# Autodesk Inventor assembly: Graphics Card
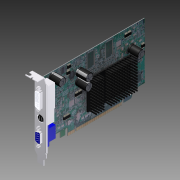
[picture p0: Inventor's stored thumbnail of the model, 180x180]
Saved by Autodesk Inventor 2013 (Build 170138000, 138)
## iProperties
Company: Autodesk Inc.
Created: 2005-12
Part Number: Graphics Card
Document SubType Name: Assembly
Designer: Autodesk Inc.
Mass: 53.2227 g
Surface Area: 677.742 cm^2
Volume: 53.2227 cm^3
Density: 1 g/cm^3
Title: Personal Computer
Author: Autodesk Inc.
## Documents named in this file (7)
- Z:\_DATEN\Personal Computer\Graphics Card\Graphics Card.iam
- Z:\_DATEN\Personal Computer\Graphics Card\Graphic Card PCB.ipt
- Z:\_DATEN\Personal Computer\Graphics Card\Graphic Card Heat Sink.ipt
- Z:\_DATEN\Personal Computer\Motherboard\Chip 5 x 3.ipt
- Z:\_DATEN\Personal Computer\Motherboard\Capacitor 3500 UF.ipt
- Z:\_DATEN\Personal Computer\Motherboard\Chip 22 x 11.ipt
- Z:\_DATEN\Personal Computer\Graphics Card\Graphic Card Sheetmetal.ipt
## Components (18 placed, 6 different names)
1. Graphic Card PCB:1 — Mate:1, Mate:2, Mate:3, Mate:4, Mate:5, Mate:6, Mate:7, Mate:8, Mate:9, Mate:10, Mate:11, Mate:12, Mate:13, Mate:14, Mate:15, Mate:16, Flush:2, Mate:18, Mate:19
2. Capacitor 3500 UF:1 — Mate:1
3. Capacitor 3500 UF:2 — Mate:2
4. Capacitor 3500 UF:3 — Mate:3
5. Graphic Card Heat Sink:1 — Mate:4
6. Capacitor 3500 UF:4 — Mate:5
7. Chip 5 x 3:1 — Mate:8
8. Chip 5 x 3:2 — Mate:7
9. Chip 5 x 3:3 — Mate:6
10. Chip 5 x 3:4 — Mate:9
11. Chip 5 x 3:5 — Mate:10
12. Chip 22 x 11:1 — Mate:11
13. Chip 22 x 11:2 — Mate:12
14. Chip 5 x 3:6 — Mate:13
15. Chip 5 x 3:7 — Mate:14
16. Chip 5 x 3:8 — Mate:15, Flush:1
17. Chip 5 x 3:9 — Mate:16, Flush:1
18. Graphic Card Sheetmetal:1 — Flush:2, Mate:18, Mate:19
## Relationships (20: Mate 18, Flush 2)
- Mate:1: Graphic Card PCB:1 ↔ Capacitor 3500 UF:1
- Mate:2: Graphic Card PCB:1 ↔ Capacitor 3500 UF:2
- Mate:3: Graphic Card PCB:1 ↔ Capacitor 3500 UF:3
- Mate:4: Graphic Card PCB:1 ↔ Graphic Card Heat Sink:1
- Mate:5: Graphic Card PCB:1 ↔ Capacitor 3500 UF:4
- Mate:6: Graphic Card PCB:1 ↔ Chip 5 x 3:3
- Mate:7: Graphic Card PCB:1 ↔ Chip 5 x 3:2
- Mate:8: Graphic Card PCB:1 ↔ Chip 5 x 3:1
- Mate:9: Graphic Card PCB:1 ↔ Chip 5 x 3:4
- Mate:10: Graphic Card PCB:1 ↔ Chip 5 x 3:5
- Mate:11: Graphic Card PCB:1 ↔ Chip 22 x 11:1
- Mate:12: Graphic Card PCB:1 ↔ Chip 22 x 11:2
- Mate:13: Graphic Card PCB:1 ↔ Chip 5 x 3:6
- Mate:14: Graphic Card PCB:1 ↔ Chip 5 x 3:7
- Mate:15: Graphic Card PCB:1 ↔ Chip 5 x 3:8
- Mate:16: Graphic Card PCB:1 ↔ Chip 5 x 3:9
- Flush:1: Chip 5 x 3:8 ↔ Chip 5 x 3:9
- Flush:2: Graphic Card PCB:1 ↔ Graphic Card Sheetmetal:1
- Mate:18: Graphic Card PCB:1 ↔ Graphic Card Sheetmetal:1
- Mate:19: Graphic Card PCB:1 ↔ Graphic Card Sheetmetal:1
